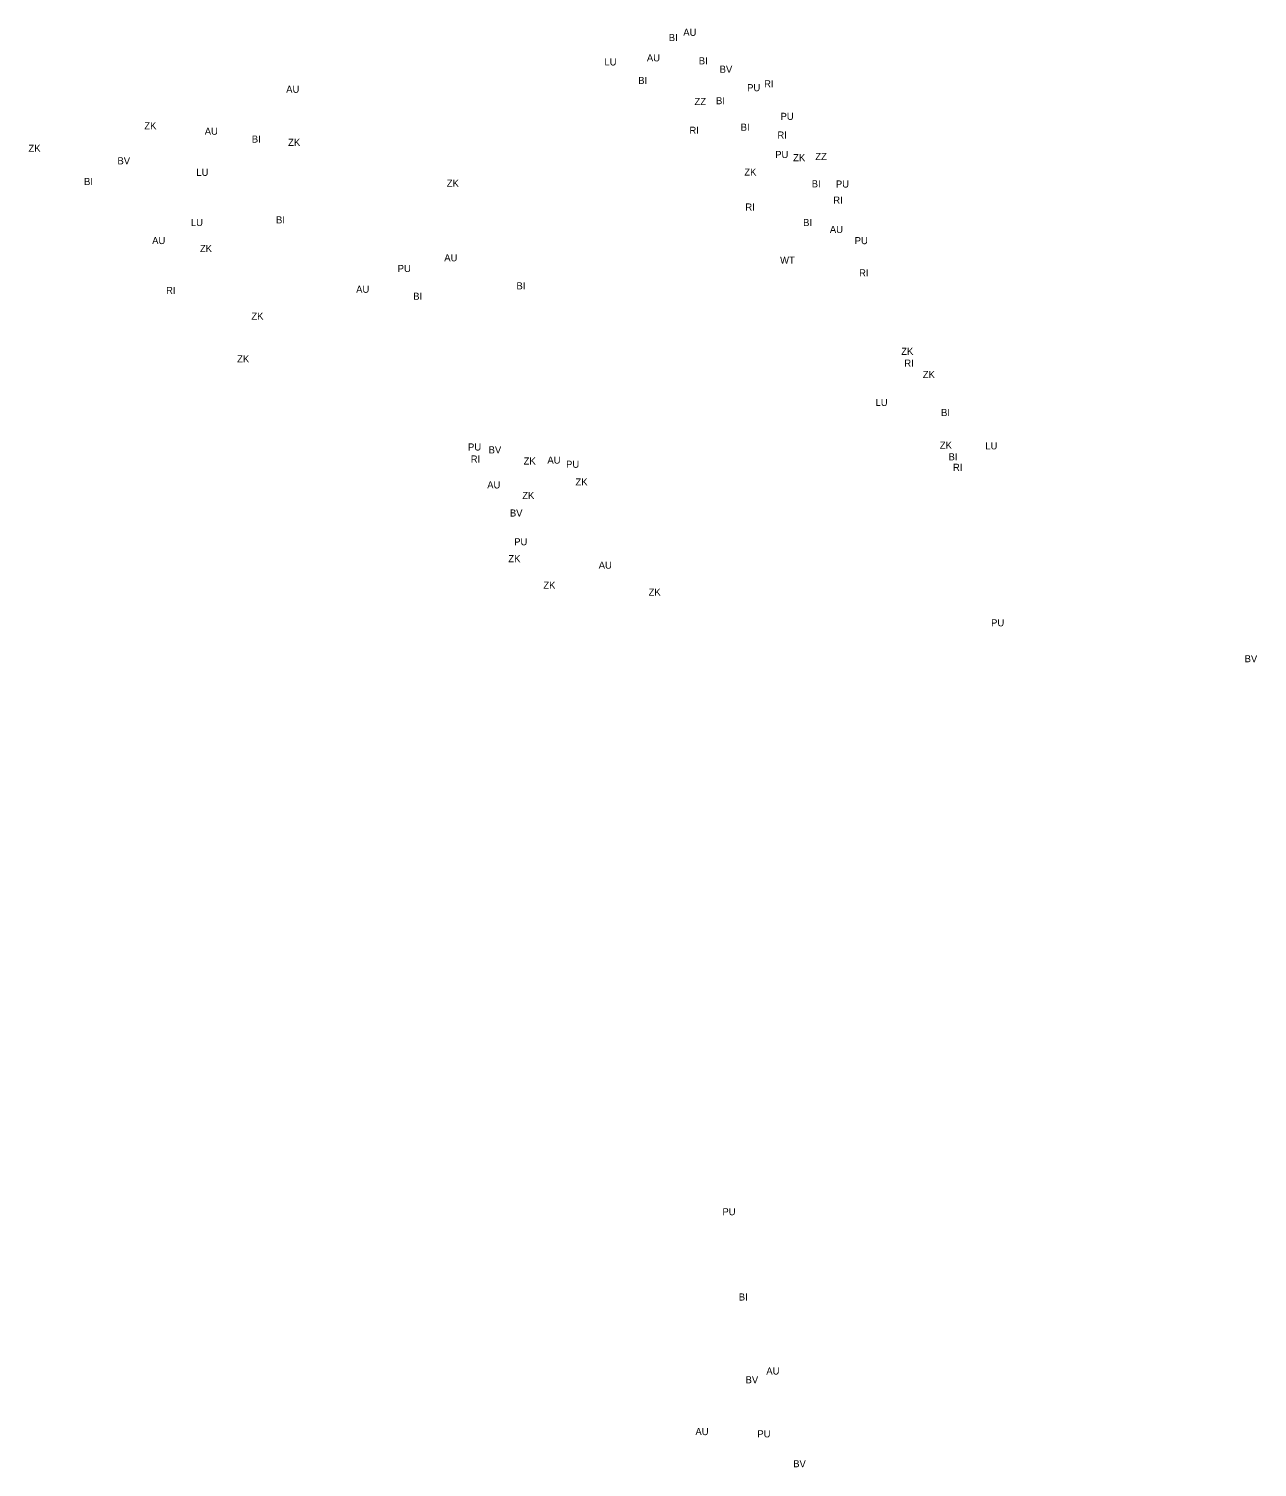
# Model space of a CAD drawing. Extents: x -439151 to -433911, y -1129946 to -1121460.
# Drawn here: x -437618 to -435882, y -1127741 to -1125709 of the extents above; entities that cross this region are included whole.
import ezdxf

# ---------------------------------------------------------------- set-up
doc = ezdxf.new("R2010")
doc.units = 0
doc.layers.add('POPIS PRESTAVBA', color=7, linetype='Continuous')
doc.layers.add('ZASTAVITELNA PLOCHA', color=7, linetype='Continuous')

msp = doc.modelspace()

# ---------------------------------------------------------------- texts
at = {"layer": 'POPIS PRESTAVBA'}
for s, p in [('AU', (-436693, -1125718.6)), ('AU', (-436744.4, -1125754.7)), ('LU', (-436804.4, -1125760.5)), ('BI', (-436671.1, -1125758.9)), ('BI', (-436756.7, -1125786.6)), ('RI', (-436578.8, -1125791.3)), ('AU', (-437254, -1125799.1)), ('ZZ', (-436677.2, -1125816.5)), ('PU', (-436602.8, -1125796.9)), ('ZK', (-437454.5, -1125850.7)), ('RI', (-436684.3, -1125857.1)), ('BI', (-436611.9, -1125852.7)), ('AU', (-437369.1, -1125858.4)), ('BI', (-437302.6, -1125869.5)), ('ZK', (-437251.3, -1125874.1)), ('RI', (-436560, -1125863.8)), ('ZK', (-437618.1, -1125882.5)), ('PU', (-436563.1, -1125891.3)), ('ZK', (-436537.8, -1125895.8)), ('ZZ', (-436506.5, -1125894.1)), ('BV', (-437492.4, -1125900.2)), ('LU', (-437381, -1125916.5)), ('ZK', (-436606.8, -1125916.1)), ('BI', (-437539.6, -1125929.5)), ('ZK', (-437027.2, -1125931.9)), ('PU', (-436477.4, -1125933)), ('RI', (-436481.1, -1125955.7)), ('RI', (-436605.3, -1125965.5)), ('LU', (-437388.7, -1125987.3)), ('BI', (-437268.4, -1125983.7)), ('AU', (-436485.9, -1125997.2)), ('AU', (-437443.4, -1126012.9)), ('PU', (-436450.8, -1126013)), ('ZK', (-437375.9, -1126024.2)), ('AU', (-437030.7, -1126037.2)), ('WT', (-436556.2, -1126040.6)), ('PU', (-437096.5, -1126052.4)), ('RI', (-436444.6, -1126058.6)), ('BI', (-436928.7, -1126076.9)), ('RI', (-437423.7, -1126083.3)), ('AU', (-437155.2, -1126081.7)), ('BI', (-437074.6, -1126091.6)), ('ZK', (-437303.2, -1126119.7)), ('ZK', (-437323.3, -1126180.1)), ('ZK', (-436385.1, -1126169.4)), ('RI', (-436380.7, -1126186.2)), ('ZK', (-436354.6, -1126202.2)), ('LU', (-436421.4, -1126241.6)), ('BI', (-436328.8, -1126255.9)), ('PU', (-436997.1, -1126304.6)), ('ZK', (-436330.5, -1126302.1)), ('LU', (-436266.3, -1126302.9)), ('RI', (-436993.3, -1126321.6)), ('BV', (-436968, -1126308.7)), ('ZK', (-436918.6, -1126324.4)), ('AU', (-436885, -1126323.1)), ('BI', (-436318.2, -1126318.5)), ('PU', (-436858.6, -1126329)), ('RI', (-436312, -1126333.3)), ('AU', (-436970, -1126358.2)), ('ZK', (-436845.3, -1126354)), ('ZK', (-436920.5, -1126373.1)), ('BV', (-436938, -1126397.9)), ('PU', (-436931.9, -1126438.5)), ('ZK', (-436940.2, -1126462.4)), ('AU', (-436812.5, -1126471.6)), ('ZK', (-436890.7, -1126499.9)), ('ZK', (-436742, -1126509.7)), ('PU', (-436258.1, -1126553)), ('BV', (-435899.9, -1126603.8)), ('PU', (-436637.7, -1127385.2)), ('BI', (-436614.6, -1127505.7)), ('BV', (-436605, -1127622.7)), ('AU', (-436575.7, -1127610.3)), ('AU', (-436675.8, -1127695.9)), ('PU', (-436588.3, -1127699.1)), ('BV', (-436537.7, -1127741.3))]:
    msp.add_text(s, height=10, dxfattribs=at).set_placement(p)
at = {"layer": 'ZASTAVITELNA PLOCHA'}
for s, p in [('BI', (-436713.5, -1125726)), ('BV', (-436641.6, -1125770.8)), ('BI', (-436646.7, -1125815.3)), ('PU', (-436555.6, -1125837.4)), ('BI', (-436511.5, -1125932.7)), ('BI', (-436523.7, -1125987.5))]:
    msp.add_text(s, height=10, dxfattribs=at).set_placement(p)

doc.saveas('drawing.dxf')
